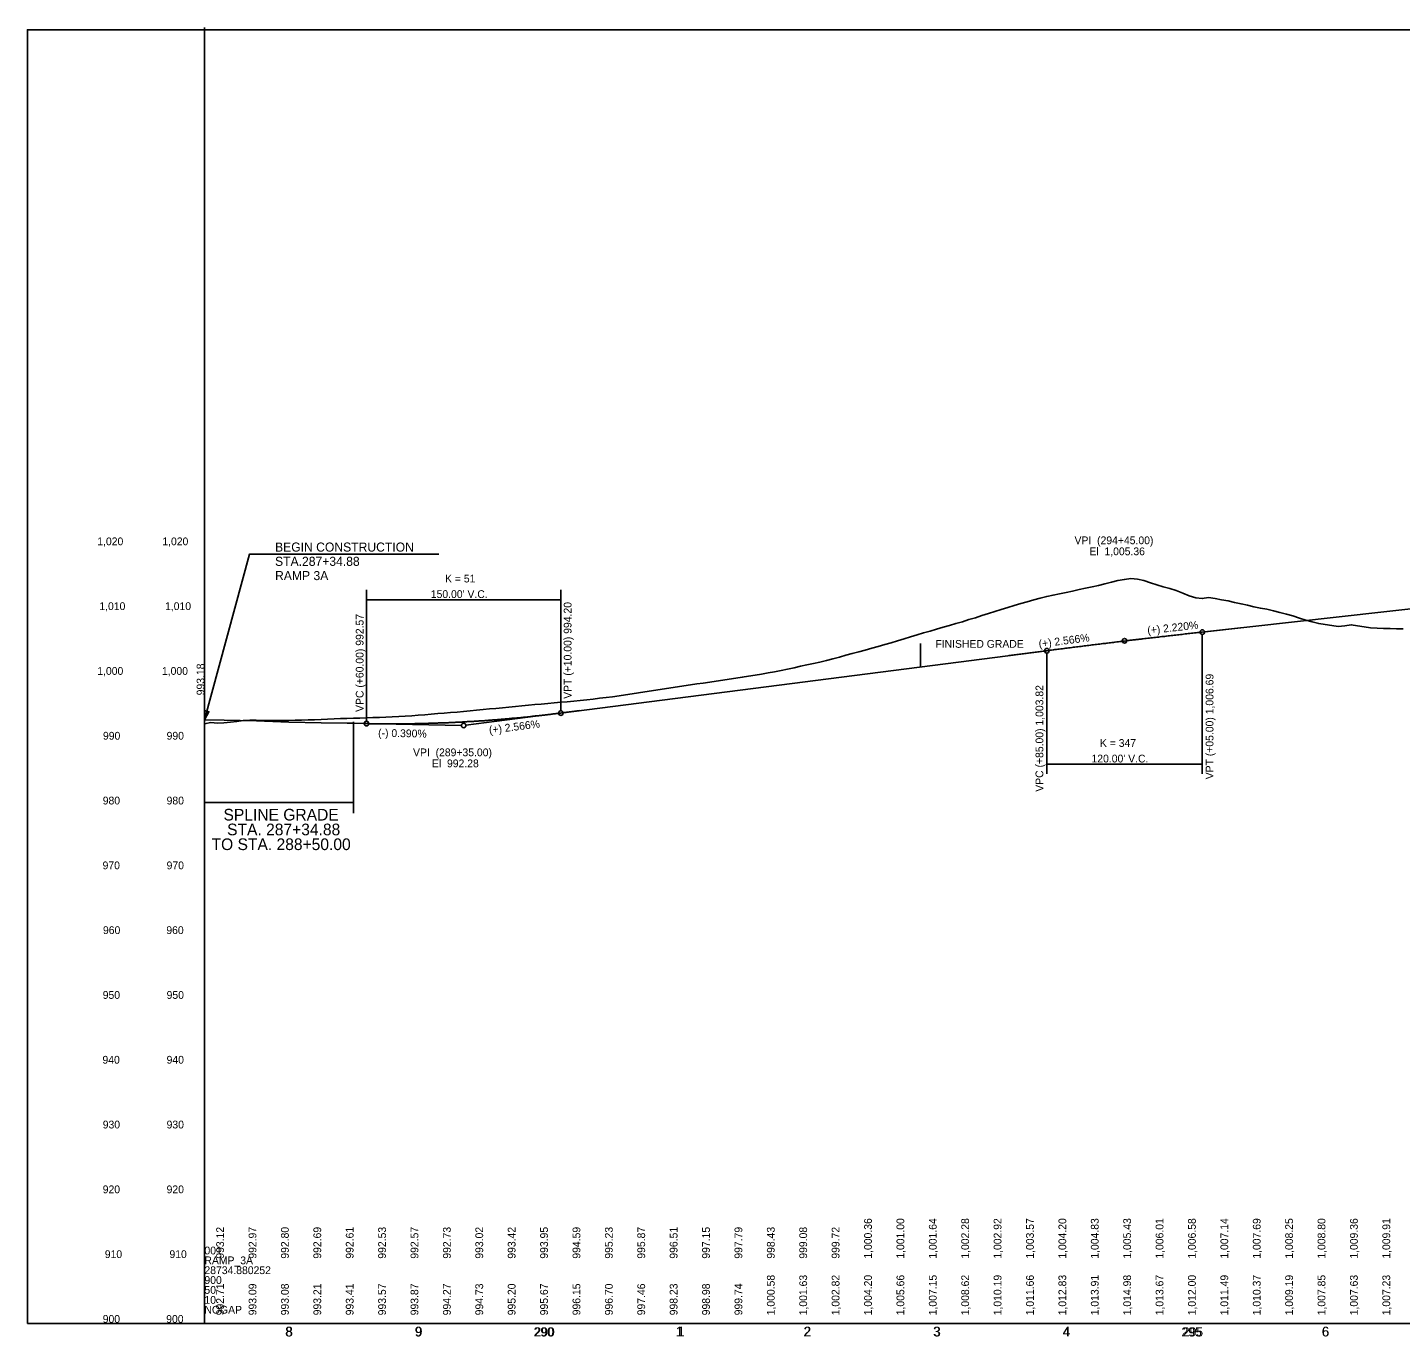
# Model space of a CAD drawing. Extents: x 112 to 16977479, y 1011 to 12562669.
# Drawn here: x 16972979 to 16974038, y 12561659 to 12562669 of the extents above; entities that cross this region are included whole.
import ezdxf

# ---------------------------------------------------------------- set-up
doc = ezdxf.new("R2010")
doc.units = 0
for name, color, linetype in [('Default', 7, 'Continuous'), ('RD_DDB_ElevTX', 7, 'Continuous'), ('RD_DDB_GradeTX', 7, 'Continuous'), ('RD_DDB_PI', 7, 'Continuous'), ('RD_DDB_Pr_Tx', 7, 'Continuous'), ('RD_DDB_Profile_EX', 7, 'Continuous'), ('RD_DDB_Profile_PR', 7, 'Continuous'), ('RD_DDB_StaTX', 7, 'Continuous'), ('RD_DDB_StripGrade', 7, 'Continuous'), ('RD_DDB_StripGrade_EX', 7, 'Continuous'), ('RD_DDB_StripGrade_PR', 7, 'Continuous'), ('RD_DDB_VCLbl', 7, 'Continuous'), ('RD_GPK_Profile_Cell', 7, 'Continuous'), ('RD_TX_Profile', 7, 'Continuous')]:
    doc.layers.add(name, color=color, linetype=linetype)

msp = doc.modelspace()

# ---------------------------------------------------------------- linework, layer by layer
at = {"layer": 'Default'}
msp.add_lwpolyline([(16972978.7, 12561668.9), (16974478.7, 12561668.9), (16974478.7, 12562667.2), (16972978.7, 12562667.2)], close=True, dxfattribs=at)
at = {"layer": 'RD_DDB_PI'}
for p, q in [((16973914.8, 12562205.7), (16973827.1, 12562195.9)), ((16973736.1, 12562184.3), (16973823.7, 12562195.5)), ((16973404.7, 12562141.8), (16973317.1, 12562130.5)), ((16973225.4, 12562132.1), (16973313.6, 12562130.4))]:
    msp.add_line(p, q, dxfattribs=at)
for centre in [(16973825.4, 12562195.7), (16973315.4, 12562130.3)]:
    msp.add_circle(centre, 1.75, dxfattribs=at)
at = {"layer": 'RD_DDB_Pr_Tx'}
msp.add_line((16973667.9, 12562193.6), (16973667.9, 12562175.5), dxfattribs=at)
at = {"layer": 'RD_DDB_Profile_EX'}
for points in [[(16973615.3, 12562185.8), (16973620.3, 12562187.1), (16973625.3, 12562188.4), (16973630.3, 12562189.9), (16973635.3, 12562191.3), (16973640.3, 12562192.8), (16973645.3, 12562194.2), (16973650.3, 12562195.7), (16973655.3, 12562197.2), (16973660.3, 12562198.7), (16973665.3, 12562200.2), (16973670.3, 12562201.7), (16973675.3, 12562203.2), (16973680.3, 12562204.7), (16973685.3, 12562206.1), (16973690.3, 12562207.5), (16973695.3, 12562208.9), (16973700.3, 12562210.4), (16973705.3, 12562212), (16973710.3, 12562213.5), (16973715.3, 12562215.1), (16973720.3, 12562216.7), (16973725.3, 12562218.3), (16973730.3, 12562219.9), (16973735.3, 12562221.4), (16973740.3, 12562222.9), (16973745.3, 12562224.4), (16973750.3, 12562225.8), (16973755.3, 12562227.2), (16973760.3, 12562228.6), (16973765.3, 12562229.9), (16973770.3, 12562231), (16973775.3, 12562232), (16973780.3, 12562233), (16973785.3, 12562234.1), (16973790.3, 12562235.2), (16973795.3, 12562236.3), (16973800.3, 12562237.3), (16973805.3, 12562238.4), (16973810.3, 12562239.7), (16973815.3, 12562240.9), (16973820.3, 12562242.1), (16973825.3, 12562243), (16973830.3, 12562243.8), (16973835.3, 12562243.2), (16973840.3, 12562242.2), (16973845.3, 12562240.5), (16973850.3, 12562238.9), (16973855.3, 12562237.3), (16973860.3, 12562236), (16973865.3, 12562234.6), (16973870.3, 12562232.4), (16973875.3, 12562230.3), (16973880.3, 12562228.9), (16973885.3, 12562228.3), (16973890.3, 12562229.2), (16973895.3, 12562228.4), (16973900.3, 12562227.3), (16973905.3, 12562226.4), (16973910.3, 12562225.2), (16973915.3, 12562224.1), (16973920.3, 12562223.2), (16973925.3, 12562222), (16973930.3, 12562220.8), (16973935.3, 12562220), (16973940.3, 12562218.7), (16973945.3, 12562217.5), (16973950.3, 12562216.2), (16973955.3, 12562214.9), (16973960.3, 12562213.2), (16973965.3, 12562211.6), (16973970.3, 12562210.2), (16973975.3, 12562209), (16973980.3, 12562208.2), (16973985.3, 12562207.5), (16973990.3, 12562206.6), (16973995.3, 12562207.3), (16974000.3, 12562208), (16974005.3, 12562207.1), (16974010.3, 12562206.4), (16974015.3, 12562205.8), (16974020.3, 12562205.3), (16974025.3, 12562205.1), (16974030.3, 12562205.1), (16974035.3, 12562205), (16974040.3, 12562205)], [(16973115.3, 12562131.5), (16973120.3, 12562132.7), (16973125.3, 12562132), (16973130.3, 12562132.5), (16973135.3, 12562133), (16973140.3, 12562133.5), (16973145.3, 12562134.3), (16973150.3, 12562134.5), (16973155.3, 12562134.4), (16973160.3, 12562134.2), (16973165.3, 12562134.1), (16973170.3, 12562134.2), (16973175.3, 12562134.2), (16973180.3, 12562134.3), (16973185.3, 12562134.4), (16973190.3, 12562134.5), (16973195.3, 12562134.7), (16973200.3, 12562134.8), (16973205.3, 12562135), (16973210.3, 12562135.2), (16973215.3, 12562135.4), (16973220.3, 12562135.6), (16973225.3, 12562135.8), (16973230.3, 12562136), (16973235.3, 12562136.1), (16973240.3, 12562136.3), (16973245.3, 12562136.5), (16973250.3, 12562136.6), (16973255.3, 12562136.8), (16973260.3, 12562137), (16973265.3, 12562137.2), (16973270.3, 12562137.6), (16973275.3, 12562137.9), (16973280.3, 12562138.3), (16973285.3, 12562138.6), (16973290.3, 12562139.1), (16973295.3, 12562139.5), (16973300.3, 12562139.9), (16973305.3, 12562140.3), (16973310.3, 12562140.6), (16973315.3, 12562141.1), (16973320.3, 12562141.6), (16973325.3, 12562142.1), (16973330.3, 12562142.6), (16973335.3, 12562143.1), (16973340.3, 12562143.5), (16973345.3, 12562144), (16973350.3, 12562144.5), (16973355.3, 12562144.9), (16973360.3, 12562145.4), (16973365.3, 12562145.9), (16973370.3, 12562146.4), (16973375.3, 12562146.8), (16973380.3, 12562147.3), (16973385.3, 12562147.8), (16973390.3, 12562148.2), (16973395.3, 12562148.7), (16973400.3, 12562149.2), (16973405.3, 12562149.7), (16973410.3, 12562150.2), (16973415.3, 12562150.7), (16973420.3, 12562151.3), (16973425.3, 12562151.9), (16973430.3, 12562152.4), (16973435.3, 12562153.1), (16973440.3, 12562153.9), (16973445.3, 12562154.7), (16973450.3, 12562155.5), (16973455.3, 12562156.2), (16973460.3, 12562157), (16973465.3, 12562157.8), (16973470.3, 12562158.6), (16973475.3, 12562159.3), (16973480.3, 12562160.1), (16973485.3, 12562160.8), (16973490.3, 12562161.6), (16973495.3, 12562162.4), (16973500.3, 12562163.1), (16973505.3, 12562163.8), (16973510.3, 12562164.6), (16973515.3, 12562165.3), (16973520.3, 12562166), (16973525.3, 12562166.8), (16973530.3, 12562167.6), (16973535.3, 12562168.5), (16973540.3, 12562169.2), (16973545.3, 12562170), (16973550.3, 12562170.9), (16973555.3, 12562171.8), (16973560.3, 12562172.7), (16973565.3, 12562173.8), (16973570.3, 12562174.9), (16973575.3, 12562176), (16973580.3, 12562177.1), (16973585.3, 12562178.2), (16973590.3, 12562179.3), (16973595.3, 12562180.5), (16973600.3, 12562181.7), (16973605.3, 12562183), (16973610.3, 12562184.5), (16973615.3, 12562185.8)]]:
    msp.add_lwpolyline(points, dxfattribs=at)
at = {"layer": 'RD_DDB_Profile_PR'}
for p, q in [((16973885.4, 12562202.4), (16974230.4, 12562240.7)), ((16973390.4, 12562139.9), (16973765.4, 12562188)), ((16973115.3, 12562134.8), (16973130.4, 12562134.5)), ((16973130.4, 12562134.5), (16973155.4, 12562133.8)), ((16973155.4, 12562133.8), (16973180.4, 12562133)), ((16973180.4, 12562133), (16973205.4, 12562132.4)), ((16973205.4, 12562132.4), (16973230.4, 12562132)), ((16973230.4, 12562132), (16973240.4, 12562131.8))]:
    msp.add_line(p, q, dxfattribs=at)
for points in [[(16973765.4, 12562188), (16973767.8, 12562188.4), (16973770.2, 12562188.7), (16973772.6, 12562189), (16973775, 12562189.3), (16973777.4, 12562189.6), (16973779.8, 12562189.9), (16973782.2, 12562190.2), (16973784.6, 12562190.5), (16973787, 12562190.8), (16973789.4, 12562191.1), (16973791.8, 12562191.4), (16973794.2, 12562191.7), (16973796.6, 12562192), (16973799, 12562192.3), (16973801.4, 12562192.6), (16973803.8, 12562192.9), (16973806.2, 12562193.2), (16973808.6, 12562193.5), (16973811, 12562193.7), (16973813.4, 12562194), (16973815.8, 12562194.3), (16973818.2, 12562194.6), (16973820.6, 12562194.9), (16973823, 12562195.2), (16973825.4, 12562195.5), (16973827.8, 12562195.8), (16973830.2, 12562196.1), (16973832.6, 12562196.3), (16973835, 12562196.6), (16973837.4, 12562196.9), (16973839.8, 12562197.2), (16973842.2, 12562197.5), (16973844.6, 12562197.8), (16973847, 12562198), (16973849.4, 12562198.3), (16973851.8, 12562198.6), (16973854.2, 12562198.9), (16973856.6, 12562199.1), (16973859, 12562199.4), (16973861.4, 12562199.7), (16973863.8, 12562200), (16973866.2, 12562200.2), (16973868.6, 12562200.5), (16973871, 12562200.8), (16973873.4, 12562201.1), (16973875.8, 12562201.3), (16973878.2, 12562201.6), (16973880.6, 12562201.9), (16973883, 12562202.1), (16973885.4, 12562202.4)], [(16973240.4, 12562131.8), (16973243.4, 12562131.7), (16973246.4, 12562131.7), (16973249.4, 12562131.6), (16973252.4, 12562131.6), (16973255.4, 12562131.6), (16973258.4, 12562131.6), (16973261.4, 12562131.6), (16973264.4, 12562131.6), (16973267.4, 12562131.6), (16973270.4, 12562131.6), (16973273.4, 12562131.7), (16973276.4, 12562131.7), (16973279.4, 12562131.8), (16973282.4, 12562131.8), (16973285.4, 12562131.9), (16973288.4, 12562132), (16973291.4, 12562132.1), (16973294.4, 12562132.2), (16973297.4, 12562132.3), (16973300.4, 12562132.4), (16973303.4, 12562132.5), (16973306.4, 12562132.6), (16973309.4, 12562132.8), (16973312.4, 12562132.9), (16973315.4, 12562133.1), (16973318.4, 12562133.3), (16973321.4, 12562133.4), (16973324.4, 12562133.6), (16973327.4, 12562133.8), (16973330.4, 12562134), (16973333.4, 12562134.2), (16973336.4, 12562134.5), (16973339.4, 12562134.7), (16973342.4, 12562134.9), (16973345.4, 12562135.2), (16973348.4, 12562135.4), (16973351.4, 12562135.7), (16973354.4, 12562136), (16973357.4, 12562136.2), (16973360.4, 12562136.5), (16973363.4, 12562136.8), (16973366.4, 12562137.1), (16973369.4, 12562137.5), (16973372.4, 12562137.8), (16973375.4, 12562138.1), (16973378.4, 12562138.5), (16973381.4, 12562138.8), (16973384.4, 12562139.2), (16973387.4, 12562139.6), (16973390.4, 12562139.9)]]:
    msp.add_spline(points, degree=3, dxfattribs=at)
at = {"layer": 'RD_DDB_StripGrade'}
for p, q in [((16973115.3, 12562062.7), (16973115.3, 12562134.8)), ((16973230.4, 12562062.7), (16973230.4, 12562133.1)), ((16973115.3, 12562070.9), (16973230.4, 12562070.9))]:
    msp.add_line(p, q, dxfattribs=at)
at = {"layer": 'RD_DDB_VCLbl'}
for p, q in [((16973240.4, 12562234.9), (16973240.4, 12562133.5)), ((16973390.4, 12562234.9), (16973390.4, 12562141.7)), ((16973240.4, 12562227.4), (16973390.4, 12562227.4)), ((16973885.4, 12562093), (16973885.4, 12562200.7)), ((16973765.4, 12562093), (16973765.4, 12562186.3)), ((16973765.4, 12562100.5), (16973885.4, 12562100.5))]:
    msp.add_line(p, q, dxfattribs=at)
for centre in [(16973885.4, 12562202.4), (16973765.4, 12562188), (16973240.4, 12562131.8), (16973390.4, 12562139.9)]:
    msp.add_circle(centre, 1.75, dxfattribs=at)
at = {"layer": 'RD_GPK_Profile_Cell'}
for q in [(16973115.3, 12562668.9), (16977337.9, 12561668.9), (16973115.3, 12561668.9)]:
    msp.add_line((16973115.3, 12561668.9), q, dxfattribs=at)
at = {"layer": 'RD_TX_Profile'}
msp.add_line((16973296.3, 12562262.5), (16973165.8, 12562262.5), dxfattribs=at)
msp.add_lwpolyline([(16973165.8, 12562262.5), (16973150, 12562262.5), (16973115.3, 12562134.8)], dxfattribs=at)
msp.add_lwpolyline([(16973115.3, 12562141.8), (16973115.3, 12562134.8), (16973118.8, 12562140.9)], close=True, dxfattribs=at)

# ---------------------------------------------------------------- texts
at = {"layer": 'RD_DDB_ElevTX'}
for s, p in [('1,020', (16973032.6, 12562269.4)), ('1,020', (16973032.6, 12562269.4)), ('1,020', (16973082.8, 12562269.4)), ('1,010', (16973034.2, 12562219.4)), ('1,010', (16973034.2, 12562219.4)), ('1,010', (16973084.9, 12562219.4)), ('1,000', (16973032.6, 12562169.4)), ('1,000', (16973032.6, 12562169.4)), ('1,000', (16973082.5, 12562169.4)), ('990', (16973037, 12562119.4)), ('990', (16973037, 12562119.4)), ('990', (16973086.1, 12562119.4)), ('980', (16973036.8, 12562069.4)), ('980', (16973036.8, 12562069.4)), ('980', (16973086.1, 12562069.4)), ('970', (16973036.7, 12562019.4)), ('970', (16973036.7, 12562019.4)), ('970', (16973086.1, 12562019.4)), ('960', (16973037, 12561969.4)), ('960', (16973037, 12561969.4)), ('960', (16973085.9, 12561969.4)), ('950', (16973036.8, 12561919.4)), ('950', (16973036.8, 12561919.4)), ('950', (16973086.1, 12561919.4)), ('940', (16973036.6, 12561869.4)), ('940', (16973036.6, 12561869.4)), ('940', (16973086.1, 12561869.4)), ('930', (16973036.8, 12561819.4)), ('930', (16973036.8, 12561819.4)), ('930', (16973086.1, 12561819.4)), ('920', (16973036.8, 12561769.4)), ('920', (16973036.8, 12561769.4)), ('920', (16973086.1, 12561769.4)), ('910', (16973038.4, 12561719.4)), ('910', (16973038.4, 12561719.4)), ('910', (16973088.3, 12561719.4)), ('900', (16973036.8, 12561669.4)), ('900', (16973036.8, 12561669.4)), ('900', (16973085.8, 12561669.4))]:
    msp.add_text(s, height=6, dxfattribs=at).set_placement(p)
at = {"layer": 'RD_DDB_GradeTX'}
for s, rotation, p in [('(+) 2.220%', 6.3339, (16973843.3, 12562200.7)), ('(+) 2.566%', 7.3104, (16973759.5, 12562190.3)), ('(+) 2.566%', 7.3104, (16973335.3, 12562123.8)), ('(-) 0.390%', 358.883, (16973249.3, 12562121.7))]:
    msp.add_text(s, height=6, rotation=rotation, dxfattribs=at).set_placement(p)
at = {"layer": 'RD_DDB_PI'}
for s, p in [('VPI  (294+45.00)', (16973786.8, 12562270.2)), ('El  1,005.36', (16973798.3, 12562261.7)), ('VPI  (289+35.00)', (16973276.3, 12562106.6)), ('El  992.28', (16973290.9, 12562098.1))]:
    msp.add_text(s, height=6, dxfattribs=at).set_placement(p)
msp.add_text('993.18', height=6, rotation=90, dxfattribs=at).set_placement((16973115.3, 12562153.6))
at = {"layer": 'RD_DDB_Pr_Tx'}
msp.add_text('FINISHED GRADE', height=6, dxfattribs=at).set_placement((16973679.4, 12562190.3))
at = {"layer": 'RD_DDB_StaTX'}
for s, height, p in [('8', 7.5, (16973177.6, 12561658.9)), ('8', 7.5, (16973177.6, 12561658.9)), ('8', 7.5, (16973178, 12561658.9)), ('9', 7.5, (16973277.6, 12561658.9)), ('9', 7.5, (16973277.6, 12561658.9)), ('9', 7.5, (16973278, 12561658.9)), ('1', 7.5, (16973479.1, 12561658.9)), ('1', 7.5, (16973479.1, 12561658.9)), ('1', 7.5, (16973480.4, 12561658.9)), ('2', 7.5, (16973577.6, 12561658.9)), ('2', 7.5, (16973577.6, 12561658.9)), ('2', 7.5, (16973578, 12561658.9)), ('3', 7.5, (16973677.6, 12561658.9)), ('3', 7.5, (16973677.6, 12561658.9)), ('3', 7.5, (16973678, 12561658.9)), ('4', 7.5, (16973777.6, 12561658.9)), ('4', 7.5, (16973777.6, 12561658.9)), ('4', 7.5, (16973778, 12561658.9)), ('6', 7.5, (16973977.6, 12561658.9)), ('6', 7.5, (16973977.6, 12561658.9)), ('6', 7.5, (16973977.8, 12561658.9)), ('290', 7, (16973369.3, 12561658.9)), ('290', 7, (16973369.3, 12561658.9)), ('290', 7, (16973370, 12561658.9)), ('295', 7, (16973869.3, 12561658.9)), ('295', 7, (16973869.3, 12561658.9)), ('295', 7, (16973870.4, 12561658.9))]:
    msp.add_text(s, height=height, dxfattribs=at).set_placement(p)
at = {"layer": 'RD_DDB_StripGrade'}
for s, p in [('SPLINE GRADE', (16973130, 12562057)), ('STA. 287+34.88', (16973132.8, 12562045.6)), ('TO STA. 288+50.00', (16973120.8, 12562034.2))]:
    msp.add_text(s, height=9, dxfattribs=at).set_placement(p)
at = {"layer": 'RD_DDB_StripGrade_EX'}
for s, p in [('992.71', (16973130.4, 12561675.2)), ('993.09', (16973155.4, 12561675.2)), ('993.08', (16973180.4, 12561675.2)), ('993.21', (16973205.4, 12561675.2)), ('993.41', (16973230.4, 12561675.2)), ('993.57', (16973255.4, 12561675.2)), ('993.87', (16973280.4, 12561675.2)), ('994.27', (16973305.4, 12561675.2)), ('994.73', (16973330.4, 12561675.2)), ('995.20', (16973355.4, 12561675.2)), ('995.67', (16973380.4, 12561675.2)), ('996.15', (16973405.4, 12561675.2)), ('996.70', (16973430.4, 12561675.2)), ('997.46', (16973455.4, 12561675.2)), ('998.23', (16973480.4, 12561675.2)), ('998.98', (16973505.4, 12561675.2)), ('999.74', (16973530.4, 12561675.2)), ('1,000.58', (16973555.4, 12561675.2)), ('1,001.63', (16973580.4, 12561675.2)), ('1,002.82', (16973605.4, 12561675.2)), ('1,004.20', (16973630.4, 12561675.2)), ('1,005.66', (16973655.4, 12561675.2)), ('1,007.15', (16973680.4, 12561675.2)), ('1,008.62', (16973705.4, 12561675.2)), ('1,010.19', (16973730.4, 12561675.2)), ('1,011.66', (16973755.4, 12561675.2)), ('1,012.83', (16973780.4, 12561675.2)), ('1,013.91', (16973805.4, 12561675.2)), ('1,014.98', (16973830.4, 12561675.2)), ('1,013.67', (16973855.4, 12561675.2)), ('1,012.00', (16973880.4, 12561675.2)), ('1,011.49', (16973905.4, 12561675.2)), ('1,010.37', (16973930.4, 12561675.2)), ('1,009.19', (16973955.4, 12561675.2)), ('1,007.85', (16973980.4, 12561675.2)), ('1,007.63', (16974005.4, 12561675.2)), ('1,007.23', (16974030.4, 12561675.2))]:
    msp.add_text(s, height=6, rotation=90, dxfattribs=at).set_placement(p)
at = {"layer": 'RD_DDB_StripGrade_PR'}
for s, p in [('993.12', (16973130.4, 12561718.9)), ('992.97', (16973155.4, 12561718.9)), ('992.80', (16973180.4, 12561718.9)), ('992.69', (16973205.4, 12561718.9)), ('992.61', (16973230.4, 12561718.9)), ('992.53', (16973255.4, 12561718.9)), ('992.57', (16973280.4, 12561718.9)), ('992.73', (16973305.4, 12561718.9)), ('993.02', (16973330.4, 12561718.9)), ('993.42', (16973355.4, 12561718.9)), ('993.95', (16973380.4, 12561718.9)), ('994.59', (16973405.4, 12561718.9)), ('995.23', (16973430.4, 12561718.9)), ('995.87', (16973455.4, 12561718.9)), ('996.51', (16973480.4, 12561718.9)), ('997.15', (16973505.4, 12561718.9)), ('997.79', (16973530.4, 12561718.9)), ('998.43', (16973555.4, 12561718.9)), ('999.08', (16973580.4, 12561718.9)), ('999.72', (16973605.4, 12561718.9)), ('1,000.36', (16973630.4, 12561718.9)), ('1,001.00', (16973655.4, 12561718.9)), ('1,001.64', (16973680.4, 12561718.9)), ('1,002.28', (16973705.4, 12561718.9)), ('1,002.92', (16973730.4, 12561718.9)), ('1,003.57', (16973755.4, 12561718.9)), ('1,004.20', (16973780.4, 12561718.9)), ('1,004.83', (16973805.4, 12561718.9)), ('1,005.43', (16973830.4, 12561718.9)), ('1,006.01', (16973855.4, 12561718.9)), ('1,006.58', (16973880.4, 12561718.9)), ('1,007.14', (16973905.4, 12561718.9)), ('1,007.69', (16973930.4, 12561718.9)), ('1,008.25', (16973955.4, 12561718.9)), ('1,008.80', (16973980.4, 12561718.9)), ('1,009.36', (16974005.4, 12561718.9)), ('1,009.91', (16974030.4, 12561718.9))]:
    msp.add_text(s, height=6, rotation=90, dxfattribs=at).set_placement(p)
at = {"layer": 'RD_DDB_VCLbl'}
for s, p in [('K = 51', (16973301, 12562240.7)), ("150.00' V.C.", (16973290, 12562228.7)), ('K = 347', (16973806.4, 12562113.8)), ("120.00' V.C.", (16973799.9, 12562101.8))]:
    msp.add_text(s, height=6, dxfattribs=at).set_placement(p)
for s, p in [('VPT (+10.00) 994.20', (16973398.6, 12562150.9)), ('VPC (+60.00) 992.57', (16973238.1, 12562140.8)), ('VPT (+05.00) 1,006.69', (16973894, 12562088.8)), ('VPC (+85.00) 1,003.82', (16973762.7, 12562079.2))]:
    msp.add_text(s, height=6, rotation=90, dxfattribs=at).set_placement(p)
at = {"layer": 'RD_GPK_Profile_Cell'}
for s, p in [('001', (16973115.3, 12561722.2)), ('RAMP_3A', (16973115.3, 12561714.6)), ('28734.880252', (16973115.3, 12561707)), ('900', (16973115.3, 12561699.4)), ('50', (16973115.3, 12561691.8)), ('10', (16973115.3, 12561684.1)), ('NOGAP', (16973115.3, 12561676.5))]:
    msp.add_text(s, height=6, dxfattribs=at).set_placement(p)
at = {"layer": 'RD_TX_Profile'}
for s, p in [('BEGIN CONSTRUCTION', (16973169.8, 12562264.5)), ('STA.287+34.88', (16973169.8, 12562253.5)), ('RAMP 3A', (16973169.8, 12562242.5))]:
    msp.add_text(s, height=7, dxfattribs=at).set_placement(p)

doc.saveas('drawing.dxf')
